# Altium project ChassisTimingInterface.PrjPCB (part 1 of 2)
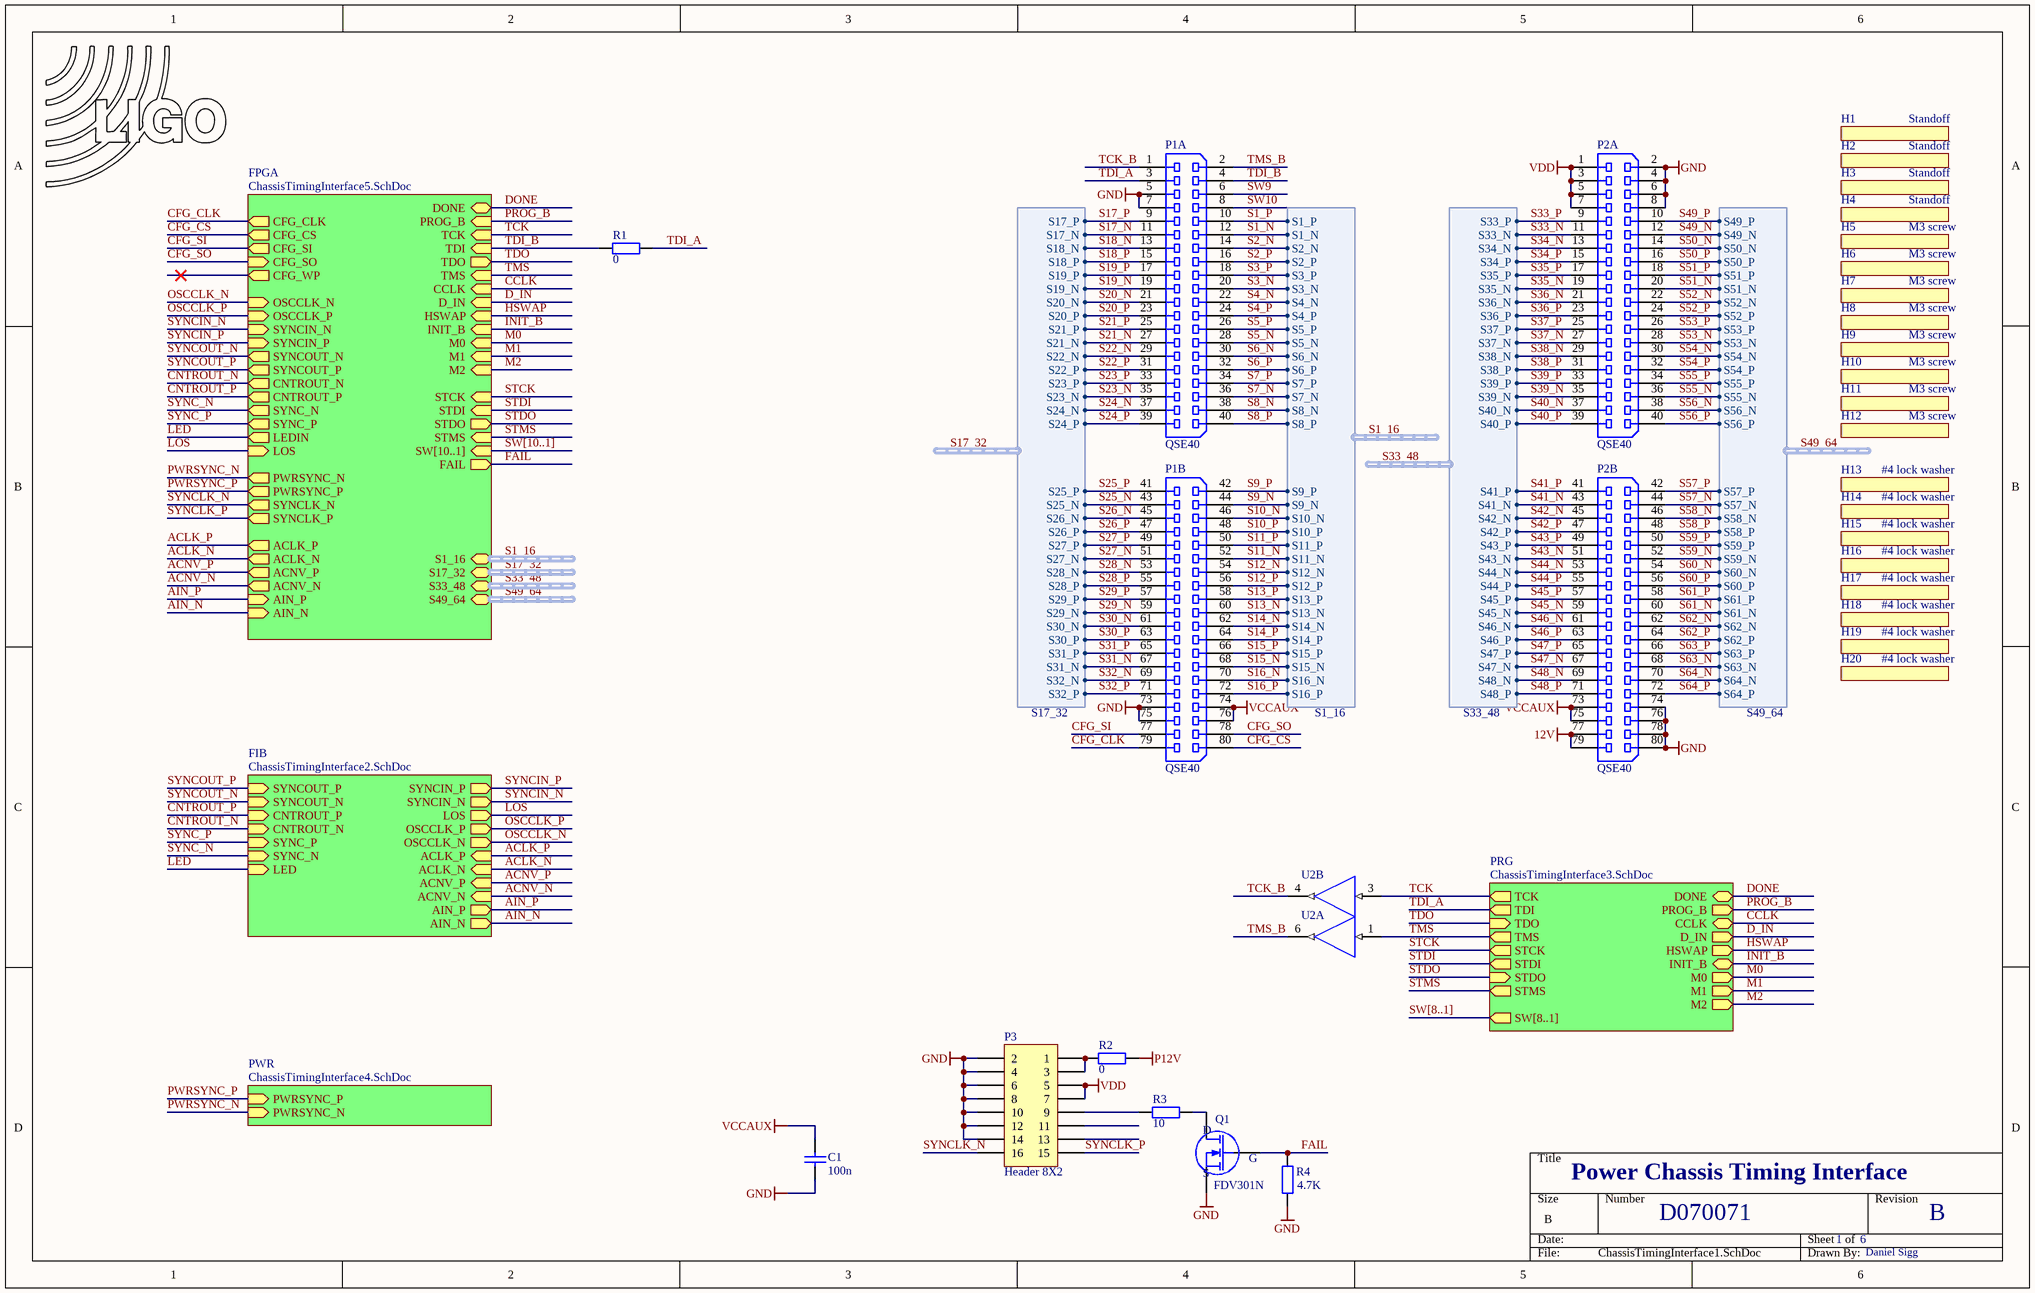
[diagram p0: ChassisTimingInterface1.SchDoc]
6 sheets, 254 parts. Net scope: hierarchical (ports join the sheet entries above them; power ports are global).
Board file: ChassisTimingInterface.PcbDoc
Sheets:
  ChassisTimingInterface1.SchDoc
    FIB = ChassisTimingInterface2.SchDoc
    PWR = ChassisTimingInterface4.SchDoc
    PRG = ChassisTimingInterface3.SchDoc
    FPGA = ChassisTimingInterface5.SchDoc
      U_FPGA_U1_Auto = FPGA_U1_Auto.SchDoc

## Sheet ChassisTimingInterface1.SchDoc: D070071
size B; Engineer: Daniel Sigg; Revision: B; SheetNumber: 1; SheetTotal: 6; PageSetup: Record=PageOptions|CenterHorizontal=True|CenterVertical=True|PrintScale=0.72|XCorrection=1.00|YCorrection=1.00|PrintKind=0|BorderSize=5000000|LeftOffset=0|BottomOffset=0|Orientation=2|PaperLength=1000|PaperWidth=1000|Scale=100|PaperSource=7|PrintQuality=-4|MediaType=1|DitherType=10|PaperKind=Tabloid|PrintScaleMode=1

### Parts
C1  100n  [CC2013-0805]
H1  Standoff  (mechanical)
H2  Standoff  (mechanical)
H3  Standoff  (mechanical)
H4  Standoff  (mechanical)
H5  M3 screw  (mechanical)
H6  M3 screw  (mechanical)
H7  M3 screw  (mechanical)
H8  M3 screw  (mechanical)
H9  M3 screw  (mechanical)
H10  M3 screw  (mechanical)
H11  M3 screw  (mechanical)
H12  M3 screw  (mechanical)
H13  #4 lock washer  (mechanical)
H14  #4 lock washer  (mechanical)
H15  #4 lock washer  (mechanical)
H16  #4 lock washer  (mechanical)
H17  #4 lock washer  (mechanical)
H18  #4 lock washer  (mechanical)
H19  #4 lock washer  (mechanical)
H20  #4 lock washer  (mechanical)
LOGO1  LIGO logo  [LIGO_LOGO]  (value not drawn)  (no BOM)
P1  QSE40  [QSE040]  (parts A,B of 2)
P2  QSE40  [QSE040]  (parts A,B of 2)
P3  Header 8X2  [HDR2X8]
Q1  FDV301N  [SO-G3/C2.25]
R1  0  [CR2012-0805]
R2  0  [CR2012-0805]
R3  10  [CR2012-0805]
R4  4.7K  [CR2012-0805]
U2  SN74LVC2G34  [SO-G6/E2.4]  (value not drawn)  (parts A,B of 2)

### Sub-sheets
FIB = ChassisTimingInterface2.SchDoc: SYNCIN_P (out), SYNCIN_N (out), SYNCOUT_P (in), SYNCOUT_N (in), LOS (out), OSCCLK_P (out), OSCCLK_N (out), CNTROUT_P (in), CNTROUT_N (in), SYNC_P (in), SYNC_N (in), LED (in), AIN_P (out), ACLK_P (in), AIN_N (out), ACNV_N (in), ACLK_N (in), ACNV_P (in)
FPGA = ChassisTimingInterface5.SchDoc: CCLK (in), CFG_CLK (out), CFG_CS (out), CFG_SI (out), CFG_SO (in), CFG_WP (out), CNTROUT_N (out), CNTROUT_P (out), D_IN (in), HSWAP (in), INIT_B (in), LEDIN (out), LOS (in), M0 (in), M1 (in), M2 (in), OSCCLK_N (in), OSCCLK_P (in), PWRSYNC_N (out), PWRSYNC_P (out), STCK (in), STDI (in), STDO (out), STMS (in), SW[10..1] (in), SYNC_N (out), SYNC_P (out), SYNCIN_N (in), SYNCIN_P (in), SYNCLK_N (out), SYNCLK_P (out), SYNCOUT_N (out), SYNCOUT_P (out), DONE (bidir), PROG_B (in), TCK (in), TDI (in), TDO (out), TMS (in), FAIL (out), ACLK_N (out), ACLK_P (out), ACNV_N (out), ACNV_P (out), AIN_N (in), AIN_P (in), S1_16 (harness S1_16), S17_32 (harness S17_32), S33_48 (harness S33_48), S49_64 (harness S49_64)
PRG = ChassisTimingInterface3.SchDoc: STCK (out), STDI (out), STDO (in), STMS (out), TCK (out), TDI (out), TDO (in), TMS (out), CCLK (bidir), D_IN (out), DONE (bidir), HSWAP (out), INIT_B (bidir), M0 (out), PROG_B (out), SW[8..1] (out), M1 (out), M2 (out)
PWR = ChassisTimingInterface4.SchDoc: PWRSYNC_P (in), PWRSYNC_N (in)

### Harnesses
S1_16: S1_N, S1_P, S2_N, S2_P, S3_N, S3_P, S4_N, S4_P, S5_N, S5_P, S6_N, S6_P, S7_N, S7_P, S8_N, S8_P, S9_N, S9_P, S10_N, S10_P, S11_N, S11_P, S12_N, S12_P, S13_N, S13_P, S14_N, S14_P, S15_N, S15_P, S16_N, S16_P
S17_32: S17_N, S17_P, S18_N, S18_P, S19_N, S19_P, S20_N, S20_P, S21_N, S21_P, S22_N, S22_P, S23_N, S23_P, S24_N, S24_P, S25_N, S25_P, S26_N, S26_P, S27_N, S27_P, S28_N, S28_P, S29_N, S29_P, S30_N, S30_P, S31_N, S31_P, S32_N, S32_P
S33_48: S33_P, S33_N, S34_P, S34_N, S35_P, S35_N, S36_N, S36_P, S37_P, S37_N, S38_N, S38_P, S39_P, S39_N, S40_N, S40_P, S41_P, S41_N, S42_N, S42_P, S43_P, S43_N, S44_N, S44_P, S45_P, S45_N, S46_N, S46_P, S47_P, S47_N, S48_N, S48_P
S49_64: S49_P, S49_N, S50_N, S50_P, S51_P, S51_N, S52_N, S52_P, S53_P, S53_N, S54_N, S54_P, S55_P, S55_N, S56_N, S56_P, S57_P, S57_N, S58_N, S58_P, S59_P, S59_N, S60_N, S60_P, S61_P, S61_N, S62_N, S62_P, S63_P, S63_N, S64_N, S64_P

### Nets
12V: P2.77 P2.79
GND: C1.1 P1.5 P1.7 P1.73 P1.75 P1.81 P1.82 P1.83 P1.84 P1.85 P1.86 P1.87 P1.88 P2.2 P2.4 P2.6 P2.8 P2.74 P2.76 P2.78 P2.80 P2.81 P2.82 P2.83 P2.84 P2.85 P2.86 P2.87 P2.88 P3.2 P3.4 P3.6 P3.8 P3.10 P3.12 P3.14 Q1.2(S) R4.1 U2.2(GND)
P12V: R2.2
VCCAUX: C1.2 P1.74 P1.76 P2.73 P2.75 U2.5(VCC)
VDD: P2.1 P2.3 P2.5 P2.7 P3.5 P3.7
ACLK_N: sheet FIB/ACLK_N, sheet FPGA/ACLK_N
ACLK_P: sheet FIB/ACLK_P, sheet FPGA/ACLK_P
ACNV_N: sheet FIB/ACNV_N, sheet FPGA/ACNV_N
ACNV_P: sheet FIB/ACNV_P, sheet FPGA/ACNV_P
AIN_N: sheet FIB/AIN_N, sheet FPGA/AIN_N
AIN_P: sheet FIB/AIN_P, sheet FPGA/AIN_P
CCLK: sheet PRG/CCLK, sheet FPGA/CCLK
CFG_CLK: P1.79 ; sheet FPGA/CFG_CLK
CFG_CS: P1.80 ; sheet FPGA/CFG_CS
CFG_SI: P1.77 ; sheet FPGA/CFG_SI
CFG_SO: P1.78 ; sheet FPGA/CFG_SO
CNTROUT_N: sheet FIB/CNTROUT_N, sheet FPGA/CNTROUT_N
CNTROUT_P: sheet FIB/CNTROUT_P, sheet FPGA/CNTROUT_P
D_IN: sheet PRG/D_IN, sheet FPGA/D_IN
DONE: sheet PRG/DONE, sheet FPGA/DONE
FAIL: Q1.1(G) R4.2 ; sheet FPGA/FAIL
HSWAP: sheet PRG/HSWAP, sheet FPGA/HSWAP
INIT_B: sheet PRG/INIT_B, sheet FPGA/INIT_B
LED: sheet FIB/LED, sheet FPGA/LEDIN
LOS: sheet FIB/LOS, sheet FPGA/LOS
M0: sheet PRG/M0, sheet FPGA/M0
M1: sheet PRG/M1, sheet FPGA/M1
M2: sheet PRG/M2, sheet FPGA/M2
OSCCLK_N: sheet FIB/OSCCLK_N, sheet FPGA/OSCCLK_N
OSCCLK_P: sheet FIB/OSCCLK_P, sheet FPGA/OSCCLK_P
PROG_B: sheet PRG/PROG_B, sheet FPGA/PROG_B
PWRSYNC_N: sheet PWR/PWRSYNC_N, sheet FPGA/PWRSYNC_N
PWRSYNC_P: sheet PWR/PWRSYNC_P, sheet FPGA/PWRSYNC_P
S1_N: P1.12 ; sheet FPGA/S1_16.S1_N  [project net S1_16.S1_N]
S1_P: P1.10 ; sheet FPGA/S1_16.S1_P  [project net S1_16.S1_P]
S2_N: P1.14 ; sheet FPGA/S1_16.S2_N  [project net S1_16.S2_N]
S2_P: P1.16 ; sheet FPGA/S1_16.S2_P  [project net S1_16.S2_P]
S3_N: P1.20 ; sheet FPGA/S1_16.S3_N  [project net S1_16.S3_N]
S3_P: P1.18 ; sheet FPGA/S1_16.S3_P  [project net S1_16.S3_P]
S4_N: P1.22 ; sheet FPGA/S1_16.S4_N  [project net S1_16.S4_N]
S4_P: P1.24 ; sheet FPGA/S1_16.S4_P  [project net S1_16.S4_P]
S5_N: P1.28 ; sheet FPGA/S1_16.S5_N  [project net S1_16.S5_N]
S5_P: P1.26 ; sheet FPGA/S1_16.S5_P  [project net S1_16.S5_P]
S6_N: P1.30 ; sheet FPGA/S1_16.S6_N  [project net S1_16.S6_N]
S6_P: P1.32 ; sheet FPGA/S1_16.S6_P  [project net S1_16.S6_P]
S7_N: P1.36 ; sheet FPGA/S1_16.S7_N  [project net S1_16.S7_N]
S7_P: P1.34 ; sheet FPGA/S1_16.S7_P  [project net S1_16.S7_P]
S8_N: P1.38 ; sheet FPGA/S1_16.S8_N  [project net S1_16.S8_N]
S8_P: P1.40 ; sheet FPGA/S1_16.S8_P  [project net S1_16.S8_P]
S9_N: P1.44 ; sheet FPGA/S1_16.S9_N  [project net S1_16.S9_N]
S9_P: P1.42 ; sheet FPGA/S1_16.S9_P  [project net S1_16.S9_P]
S10_N: P1.46 ; sheet FPGA/S1_16.S10_N
S10_P: P1.48 ; sheet FPGA/S1_16.S10_P
S11_N: P1.52 ; sheet FPGA/S1_16.S11_N
S11_P: P1.50 ; sheet FPGA/S1_16.S11_P
S12_N: P1.54 ; sheet FPGA/S1_16.S12_N
S12_P: P1.56 ; sheet FPGA/S1_16.S12_P
S13_N: P1.60 ; sheet FPGA/S1_16.S13_N
S13_P: P1.58 ; sheet FPGA/S1_16.S13_P
S14_N: P1.62 ; sheet FPGA/S1_16.S14_N
S14_P: P1.64 ; sheet FPGA/S1_16.S14_P
S15_N: P1.68 ; sheet FPGA/S1_16.S15_N
S15_P: P1.66 ; sheet FPGA/S1_16.S15_P
S16_N: P1.70 ; sheet FPGA/S1_16.S16_N
S16_P: P1.72 ; sheet FPGA/S1_16.S16_P
S17_N: P1.11 ; sheet FPGA/S17_32.S17_N  [project net S17_32.S17_N]
S17_P: P1.9 ; sheet FPGA/S17_32.S17_P  [project net S17_32.S17_P]
S18_N: P1.13 ; sheet FPGA/S17_32.S18_N  [project net S17_32.S18_N]
S18_P: P1.15 ; sheet FPGA/S17_32.S18_P  [project net S17_32.S18_P]
S19_N: P1.19 ; sheet FPGA/S17_32.S19_N  [project net S17_32.S19_N]
S19_P: P1.17 ; sheet FPGA/S17_32.S19_P  [project net S17_32.S19_P]
S20_N: P1.21 ; sheet FPGA/S17_32.S20_N  [project net S17_32.S20_N]
S20_P: P1.23 ; sheet FPGA/S17_32.S20_P  [project net S17_32.S20_P]
S21_N: P1.27 ; sheet FPGA/S17_32.S21_N  [project net S17_32.S21_N]
S21_P: P1.25 ; sheet FPGA/S17_32.S21_P  [project net S17_32.S21_P]
S22_N: P1.29 ; sheet FPGA/S17_32.S22_N  [project net S17_32.S22_N]
S22_P: P1.31 ; sheet FPGA/S17_32.S22_P  [project net S17_32.S22_P]
S23_N: P1.35 ; sheet FPGA/S17_32.S23_N  [project net S17_32.S23_N]
S23_P: P1.33 ; sheet FPGA/S17_32.S23_P  [project net S17_32.S23_P]
S24_N: P1.37 ; sheet FPGA/S17_32.S24_N  [project net S17_32.S24_N]
S24_P: P1.39 ; sheet FPGA/S17_32.S24_P  [project net S17_32.S24_P]
S25_N: P1.43 ; sheet FPGA/S17_32.S25_N  [project net S17_32.S25_N]
S25_P: P1.41 ; sheet FPGA/S17_32.S25_P  [project net S17_32.S25_P]
S26_N: P1.45 ; sheet FPGA/S17_32.S26_N  [project net S17_32.S26_N]
S26_P: P1.47 ; sheet FPGA/S17_32.S26_P  [project net S17_32.S26_P]
S27_N: P1.51 ; sheet FPGA/S17_32.S27_N  [project net S17_32.S27_N]
S27_P: P1.49 ; sheet FPGA/S17_32.S27_P  [project net S17_32.S27_P]
S28_N: P1.53 ; sheet FPGA/S17_32.S28_N  [project net S17_32.S28_N]
S28_P: P1.55 ; sheet FPGA/S17_32.S28_P  [project net S17_32.S28_P]
S29_N: P1.59 ; sheet FPGA/S17_32.S29_N  [project net S17_32.S29_N]
S29_P: P1.57 ; sheet FPGA/S17_32.S29_P  [project net S17_32.S29_P]
S30_N: P1.61 ; sheet FPGA/S17_32.S30_N  [project net S17_32.S30_N]
S30_P: P1.63 ; sheet FPGA/S17_32.S30_P  [project net S17_32.S30_P]
S31_N: P1.67 ; sheet FPGA/S17_32.S31_N  [project net S17_32.S31_N]
S31_P: P1.65 ; sheet FPGA/S17_32.S31_P  [project net S17_32.S31_P]
S32_N: P1.69 ; sheet FPGA/S17_32.S32_N  [project net S17_32.S32_N]
S32_P: P1.71 ; sheet FPGA/S17_32.S32_P  [project net S17_32.S32_P]
S33_N: P2.11 ; sheet FPGA/S33_48.S33_N  [project net S33_48.S33_N]
S33_P: P2.9 ; sheet FPGA/S33_48.S33_P  [project net S33_48.S33_P]
S34_N: P2.13 ; sheet FPGA/S33_48.S34_N  [project net S33_48.S34_N]
S34_P: P2.15 ; sheet FPGA/S33_48.S34_P  [project net S33_48.S34_P]
S35_N: P2.19 ; sheet FPGA/S33_48.S35_N  [project net S33_48.S35_N]
S35_P: P2.17 ; sheet FPGA/S33_48.S35_P  [project net S33_48.S35_P]
S36_N: P2.21 ; sheet FPGA/S33_48.S36_N  [project net S33_48.S36_N]
S36_P: P2.23 ; sheet FPGA/S33_48.S36_P  [project net S33_48.S36_P]
S37_N: P2.27 ; sheet FPGA/S33_48.S37_N  [project net S33_48.S37_N]
S37_P: P2.25 ; sheet FPGA/S33_48.S37_P  [project net S33_48.S37_P]
S38_N: P2.29 ; sheet FPGA/S33_48.S38_N  [project net S33_48.S38_N]
S38_P: P2.31 ; sheet FPGA/S33_48.S38_P  [project net S33_48.S38_P]
S39_N: P2.35 ; sheet FPGA/S33_48.S39_N  [project net S33_48.S39_N]
S39_P: P2.33 ; sheet FPGA/S33_48.S39_P  [project net S33_48.S39_P]
S40_N: P2.37 ; sheet FPGA/S33_48.S40_N  [project net S33_48.S40_N]
S40_P: P2.39 ; sheet FPGA/S33_48.S40_P  [project net S33_48.S40_P]
S41_N: P2.43 ; sheet FPGA/S33_48.S41_N  [project net S33_48.S41_N]
S41_P: P2.41 ; sheet FPGA/S33_48.S41_P  [project net S33_48.S41_P]
S42_N: P2.45 ; sheet FPGA/S33_48.S42_N  [project net S33_48.S42_N]
S42_P: P2.47 ; sheet FPGA/S33_48.S42_P  [project net S33_48.S42_P]
S43_N: P2.51 ; sheet FPGA/S33_48.S43_N  [project net S33_48.S43_N]
S43_P: P2.49 ; sheet FPGA/S33_48.S43_P  [project net S33_48.S43_P]
S44_N: P2.53 ; sheet FPGA/S33_48.S44_N  [project net S33_48.S44_N]
S44_P: P2.55 ; sheet FPGA/S33_48.S44_P  [project net S33_48.S44_P]
S45_N: P2.59 ; sheet FPGA/S33_48.S45_N  [project net S33_48.S45_N]
S45_P: P2.57 ; sheet FPGA/S33_48.S45_P  [project net S33_48.S45_P]
S46_N: P2.61 ; sheet FPGA/S33_48.S46_N  [project net S33_48.S46_N]
S46_P: P2.63 ; sheet FPGA/S33_48.S46_P  [project net S33_48.S46_P]
S47_N: P2.67 ; sheet FPGA/S33_48.S47_N  [project net S33_48.S47_N]
S47_P: P2.65 ; sheet FPGA/S33_48.S47_P  [project net S33_48.S47_P]
S48_N: P2.69 ; sheet FPGA/S33_48.S48_N  [project net S33_48.S48_N]
S48_P: P2.71 ; sheet FPGA/S33_48.S48_P  [project net S33_48.S48_P]
S49_N: P2.12 ; sheet FPGA/S49_64.S49_N  [project net S49_64.S49_N]
S49_P: P2.10 ; sheet FPGA/S49_64.S49_P  [project net S49_64.S49_P]
S50_N: P2.14 ; sheet FPGA/S49_64.S50_N  [project net S49_64.S50_N]
S50_P: P2.16 ; sheet FPGA/S49_64.S50_P  [project net S49_64.S50_P]
S51_N: P2.20 ; sheet FPGA/S49_64.S51_N  [project net S49_64.S51_N]
S51_P: P2.18 ; sheet FPGA/S49_64.S51_P  [project net S49_64.S51_P]
S52_N: P2.22 ; sheet FPGA/S49_64.S52_N  [project net S49_64.S52_N]
S52_P: P2.24 ; sheet FPGA/S49_64.S52_P  [project net S49_64.S52_P]
S53_N: P2.28 ; sheet FPGA/S49_64.S53_N  [project net S49_64.S53_N]
S53_P: P2.26 ; sheet FPGA/S49_64.S53_P  [project net S49_64.S53_P]
S54_N: P2.30 ; sheet FPGA/S49_64.S54_N  [project net S49_64.S54_N]
S54_P: P2.32 ; sheet FPGA/S49_64.S54_P  [project net S49_64.S54_P]
S55_N: P2.36 ; sheet FPGA/S49_64.S55_N  [project net S49_64.S55_N]
S55_P: P2.34 ; sheet FPGA/S49_64.S55_P  [project net S49_64.S55_P]
S56_N: P2.38 ; sheet FPGA/S49_64.S56_N  [project net S49_64.S56_N]
S56_P: P2.40 ; sheet FPGA/S49_64.S56_P  [project net S49_64.S56_P]
S57_N: P2.44 ; sheet FPGA/S49_64.S57_N  [project net S49_64.S57_N]
S57_P: P2.42 ; sheet FPGA/S49_64.S57_P  [project net S49_64.S57_P]
S58_N: P2.46 ; sheet FPGA/S49_64.S58_N  [project net S49_64.S58_N]
S58_P: P2.48 ; sheet FPGA/S49_64.S58_P  [project net S49_64.S58_P]
S59_N: P2.52 ; sheet FPGA/S49_64.S59_N  [project net S49_64.S59_N]
S59_P: P2.50 ; sheet FPGA/S49_64.S59_P  [project net S49_64.S59_P]
S60_N: P2.54 ; sheet FPGA/S49_64.S60_N  [project net S49_64.S60_N]
S60_P: P2.56 ; sheet FPGA/S49_64.S60_P  [project net S49_64.S60_P]
S61_N: P2.60 ; sheet FPGA/S49_64.S61_N  [project net S49_64.S61_N]
S61_P: P2.58 ; sheet FPGA/S49_64.S61_P  [project net S49_64.S61_P]
S62_N: P2.62 ; sheet FPGA/S49_64.S62_N  [project net S49_64.S62_N]
S62_P: P2.64 ; sheet FPGA/S49_64.S62_P  [project net S49_64.S62_P]
S63_N: P2.68 ; sheet FPGA/S49_64.S63_N  [project net S49_64.S63_N]
S63_P: P2.66 ; sheet FPGA/S49_64.S63_P  [project net S49_64.S63_P]
S64_N: P2.70 ; sheet FPGA/S49_64.S64_N  [project net S49_64.S64_N]
S64_P: P2.72 ; sheet FPGA/S49_64.S64_P  [project net S49_64.S64_P]
STCK: sheet PRG/STCK, sheet FPGA/STCK
STDI: sheet PRG/STDI, sheet FPGA/STDI
STDO: sheet PRG/STDO, sheet FPGA/STDO
STMS: sheet PRG/STMS, sheet FPGA/STMS
SW9: P1.6
SW10: P1.8
SYNC_N: sheet FIB/SYNC_N, sheet FPGA/SYNC_N
SYNC_P: sheet FIB/SYNC_P, sheet FPGA/SYNC_P
SYNCIN_N: sheet FIB/SYNCIN_N, sheet FPGA/SYNCIN_N
SYNCIN_P: sheet FIB/SYNCIN_P, sheet FPGA/SYNCIN_P
SYNCLK_N: P3.16 ; sheet FPGA/SYNCLK_N
SYNCLK_P: P3.15 ; sheet FPGA/SYNCLK_P
SYNCOUT_N: sheet FIB/SYNCOUT_N, sheet FPGA/SYNCOUT_N
SYNCOUT_P: sheet FIB/SYNCOUT_P, sheet FPGA/SYNCOUT_P
TCK: U2.3(2A) ; sheet PRG/TCK, sheet FPGA/TCK
TCK_B: P1.1 U2.4(2Y)
TDI_A: P1.3 R1.2 ; sheet PRG/TDI
TDI_B: P1.4 R1.1 ; sheet FPGA/TDI
TDO: sheet PRG/TDO, sheet FPGA/TDO
TMS: U2.1(1A) ; sheet PRG/TMS, sheet FPGA/TMS
TMS_B: P1.2 U2.6(1Y)
NetP3_1: P3.1 P3.3 R2.1
NetP3_9: P3.9 R3.1
NetQ1_3: Q1.3(D) R3.2

Not connected (* = marked no-connect by the designer): P3 11 13

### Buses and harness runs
bus SW[8..1] = sheet PRG/SW[8..1]
bus SW[10..1] = sheet FPGA/SW[10..1]
harness S1_16 = sheet FPGA/S1_16
harness S17_32 = sheet FPGA/S17_32
harness S33_48 = sheet FPGA/S33_48
harness S49_64 = sheet FPGA/S49_64

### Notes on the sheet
- Power Chassis Timing Interface
- D070071
- B
- Daniel Sigg

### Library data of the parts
C1 = ChipCap: Capacitor, surface mount; Part Number: 478-1395-1-ND; Tolerance: 10%
H1-H4 = Partlist: Mounting hardware; Part Number: 728-FM1258-3005-A
H5-H12 = Partlist: Mounting hardware; Part Number: 48SM003
H13-H20 = Partlist: Mounting hardware; Part Number: 5721-LWI6SS
LOGO1 = LIGO_logo
P1 P2 = SAMTEC_QSE40: Samtec hi-speed socket, 0.8mm, 80 pins; Part Number: SAM8124-ND
P3 = Header 8X2: Header, 8-Pin, Dual row; Part Number: A33164-ND
Q1 = FDV301N: FDV301N, Digital FET, N-channel, SOT23; Part Number: FDV301NCT-ND
R1 R2 = ChipRes1: Resistor, surface mount; Part Number: 311-0.0ARCT-ND; Tolerance: 0.5%
R3 = ChipRes1: Resistor, surface mount; Part Number: RR12Q10DCT-ND; Tolerance: 0.5%
R4 = ChipRes1: Resistor, surface mount; Part Number: RR12P4.7KDCT-ND; Tolerance: 0.5%
U2 = SN74LVC2G34: Dual buffer; Part Number: 296-13496-1-ND

## Sheet ChassisTimingInterface2.SchDoc: D070071
size B; Revision: B; SheetNumber: 2; SheetTotal: 6
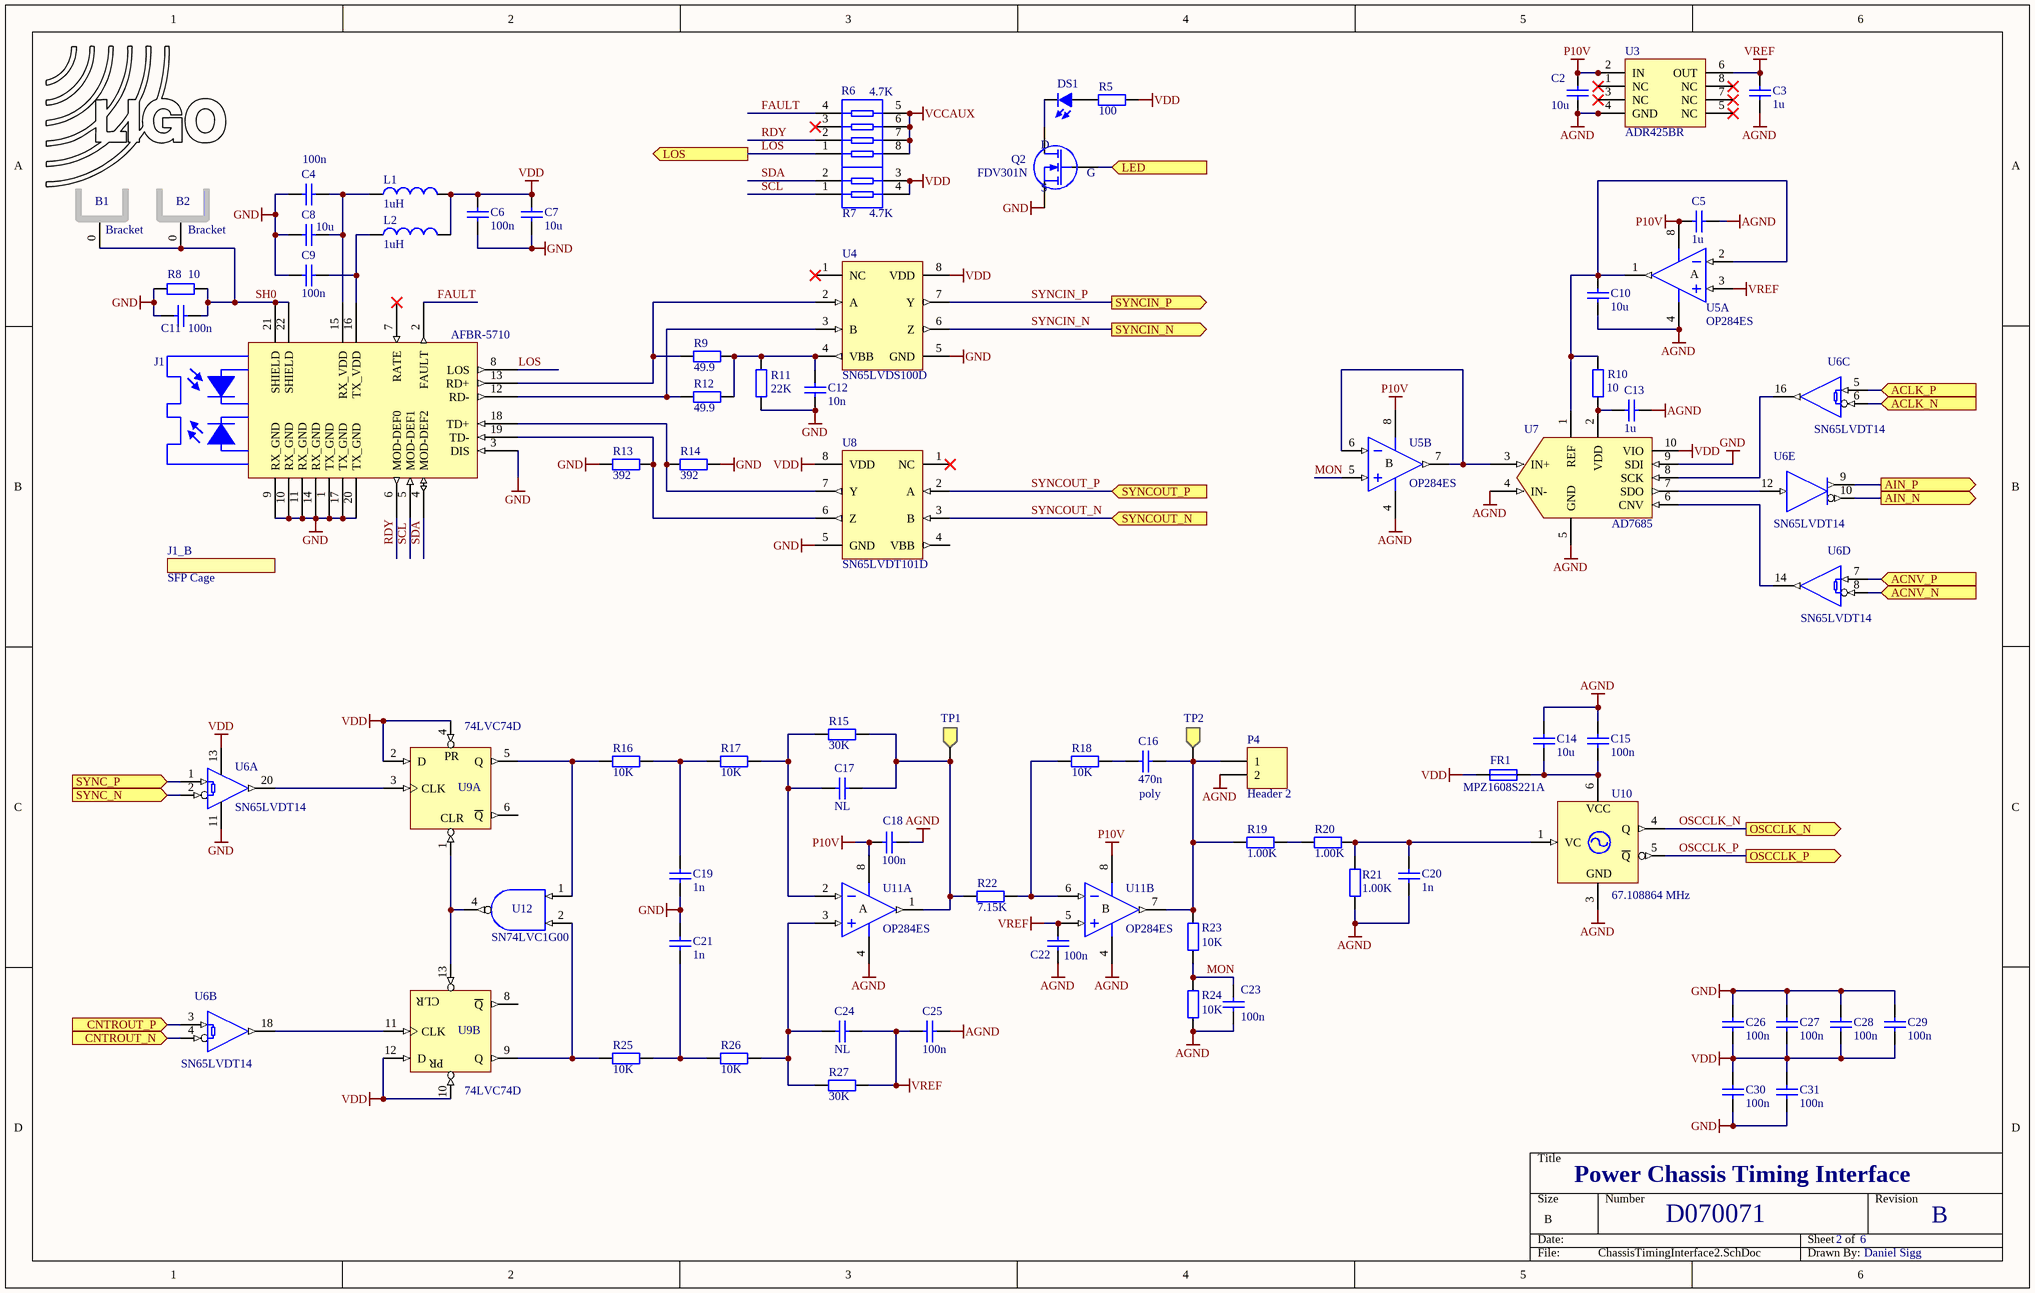
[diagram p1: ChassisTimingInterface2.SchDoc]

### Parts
B1  Bracket  [Bracket-RA_7774]
B2  Bracket  [Bracket-RA_7774]
C2  10u  [CC3216-1206]
C3  1u  [CC2013-0805]
C4  100n  [CC2013-0805]
C5  1u  [CC2013-0805]
C6  100n  [CC2013-0805]
C7  10u  [CC2013-0805]
C8  10u  [CC2013-0805]
C9  100n  [CC2013-0805]
C10  10u  [CC3216-1206]
C11  100n  [CC2013-0805]
C12  10n  [CC2013-0805]
C13  1u  [CC2013-0805]
C14  10u  [CC2013-0805]
C15  100n  [CC2013-0805]
C16  470n  [CA053035]
C17  NL  [CC2013-0805]
C18  100n  [CC2013-0805]
C19  1n  [CC2013-0805]
C20  1n  [CC2013-0805]
C21  1n  [CC2013-0805]
C22  100n  [CC2013-0805]
C23  100n  [CC2013-0805]
C24  NL  [CC2013-0805]
C25  100n  [CC2013-0805]
C26  100n  [CC2013-0805]
C27  100n  [CC2013-0805]
C28  100n  [CC2013-0805]
C29  100n  [CC2013-0805]
C30  100n  [CC2013-0805]
C31  100n  [CC2013-0805]
DS1  LED  [LED-2]  (value not drawn)
FR1  MPZ1608S221A  [CL1608-0603]
J1  AFBR-5710  [MSA/SFP2x10]
J1_B  SFP Cage  (mechanical)
L1  1uH  [CL2520-1008]
L2  1uH  [CL2520-1008]
LOGO2  LIGO logo  [LIGO_LOGO]  (value not drawn)  (graphical)
P4  Header 2  [HDR1X2]
Q2  FDV301N  [SO-G3/C2.25]
R5  100  [CR2012-0805]
R6  value 4.7K  [RES8-0.8]  (hidden comment: Resistor Array)
R7  value 4.7K  [RES4-0.8]  (hidden comment: Resistor Array)
R8  10  [CR2012-0805]
R9  49.9  [CR2012-0805]
R10  10  [CR2012-0805]
R11  22K  [CR2012-0805]
R12  49.9  [CR2012-0805]
R13  392  [CR2012-0805]
R14  392  [CR2012-0805]
R15  30K  [CR2012-0805]
R16  10K  [CR2012-0805]
R17  10K  [CR2012-0805]
R18  10K  [CR2012-0805]
R19  1.00K  [CR2012-0805]
R20  1.00K  [CR2012-0805]
R21  1.00K  [CR2012-0805]
R22  7.15K  [CR2012-0805]
R23  10K  [CR2012-0805]
R24  10K  [CR2012-0805]
R25  10K  [CR2012-0805]
R26  10K  [CR2012-0805]
R27  30K  [CR2012-0805]
TP1  Testpoint  [TP1]  (value not drawn)
TP2  Testpoint  [TP1]  (value not drawn)
U3  ADR425BR  [SO-G8]
U4  SN65LVDS100D  [SO-G8]
U5  OP284ES  [SO-G8]  (parts A,B of 2)
U6  SN65LVDT14  [TSSO6x6-G20/D6.6]  (parts A,B,C,D,E of 5)
U7  AD7685  [TSSO3x5-G10]
U8  SN65LVDT101D  [SO-G8]
U9  74LVC74D  [SO-G14]  (parts A,B of 2)
U10  67.108864 MHz  [VECTRON_C5310]
U11  OP284ES  [SO-G8]  (parts A,B of 2)
U12  SN74LVC1G00  [SO-G5/E2.4]

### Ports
ACLK_N (in), ACLK_P (in), ACNV_N (in), ACNV_P (in), AIN_N (out), AIN_P (out), CNTROUT_N (in), CNTROUT_P (in), LED (in), LOS (out), OSCCLK_N (out), OSCCLK_P (out), SYNC_N (in), SYNC_P (in), SYNCIN_N (out), SYNCIN_P (out), SYNCOUT_N (in), SYNCOUT_P (in)

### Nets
AGND: C2.2 C3.1 C5.1 C10.1 C13.2 C14.1 C15.1 C18.1 C20.2 C22.1 C23.1 C25.1 P4.2 R21.2 R24.2 U3.4(GND) U5.4(V-) U7.4(IN-) U7.5(GND) U10.3(GND) U11.4(V-)
GND: C4.1 C6.1 C7.1 C8.1 C9.1 C11.2 C12.1 C19.2 C21.1 C26.2 C27.2 C28.2 C29.2 C30.1 C31.1 J1.1(TX_GND) J1.3(DIS) J1.9(RX_GND) J1.10(RX_GND) J1.11(RX_GND) J1.14(RX_GND) J1.17(TX_GND) J1.20(TX_GND) Q2.2(S) R8.2 R11.2 R13.1 R14.2 U4.5(GND) U6.11(GND) U6.15(GND) U6.19(GND) U7.9(SDI) U8.5(GND) U9.7(GND) U12.3(GND)
P10V: C2.1 C5.2 C18.2 U3.2(IN) U5.8(V+) U11.8(V+)
VCCAUX: R6.5 R6.6 R6.7 R6.8
VDD: C6.2 C7.2 C26.1 C27.1 C28.1 C29.1 C30.2 C31.2 FR1.1 L1.2 L2.2 R5.2 R7.3 R7.4 U4.8(VDD) U6.13(VCC) U6.17(VCC) U7.10(VIO) U8.8(VDD) U9.2(D) U9.4(PR) U9.10(PR) U9.12(D) U9.14(VDD) U12.5(VDD)
VREF: C3.2 C22.2 C24.1 C25.2 R27.2 U3.6(OUT) U5.3(IN+) U11.5(IN+)
ACLK_N: U6.6(3B) ; port ACLK_N
ACLK_P: U6.5(3A) ; port ACLK_P
ACNV_N: U6.8(4B) ; port ACNV_N
ACNV_P: U6.7(4A) ; port ACNV_P
AIN_N: U6.10(5Z) ; port AIN_N
AIN_P: U6.9(5Y) ; port AIN_P
CNTROUT_N: U6.4(2B) ; port CNTROUT_N
CNTROUT_P: U6.3(2A) ; port CNTROUT_P
FAULT: J1.2(FAULT) R6.4
LED: Q2.1(G) ; port LED
LOS: J1.8(LOS) R6.1 ; port LOS
MON: C23.2 R23.2 R24.1 U5.5(IN+)
OSCCLK_N: U10.4(Q) ; port OSCCLK_N
OSCCLK_P: U10.5(~{Q}) ; port OSCCLK_P
RDY: J1.6(MOD-DEF0) R6.2
SCL: J1.5(MOD-DEF1) R7.1
SDA: J1.4(MOD-DEF2) R7.2
SH0: B1.0(GND) B2.0(GND) C11.1 J1.21(SHIELD) J1.22(SHIELD) R8.1
SYNC_N: U6.2(1B) ; port SYNC_N
SYNC_P: U6.1(1A) ; port SYNC_P
SYNCIN_N: U4.6(Z) ; port SYNCIN_N
SYNCIN_P: U4.7(Y) ; port SYNCIN_P
SYNCOUT_N: U8.3(B) ; port SYNCOUT_N
SYNCOUT_P: U8.2(A) ; port SYNCOUT_P
NetC4_2: C4.2 C8.2 J1.15(RX_VDD) L1.1
NetC9_2: C9.2 J1.16(TX_VDD) L2.1
NetC10_2: C10.2 R10.2 U5.1(OUT) U5.2(IN-) U7.1(REF)
NetC12_2: C12.2 R9.1 R11.1 R12.1 U4.4(VBB)
NetC13_1: C13.1 R10.1 U7.2(VDD)
NetC14_2: C14.2 C15.2 FR1.2 U10.6(VDD)
NetC16_1: C16.1 R18.2
NetC16_2: C16.2 P4.1 R19.2 R23.1 TP2.1 U11.7(OUT)
NetC17_1: C17.1 R15.2 R22.1 TP1.1 U11.1(OUT)
NetC17_2: C17.2 R15.1 R17.2 U11.2(IN-)
NetC19_1: C19.1 R16.2 R17.1
NetC20_1: C20.1 R20.1 R21.1 U10.1(VC)
NetC21_2: C21.2 R25.2 R26.1
NetC24_2: C24.2 R26.2 R27.1 U11.3(IN+)
NetDS1_1: DS1.1(K) Q2.3(D)
NetDS1_2: DS1.2(A) R5.1
NetJ1_12: J1.12(RD-) R12.2 U4.3(B)
NetJ1_13: J1.13(RD+) R9.2 U4.2(A)
NetJ1_18: J1.18(TD+) R14.1 U8.7(Y)
NetJ1_19: J1.19(TD-) R13.2 U8.6(Z)
NetR16_1: R16.1 U9.5(Q) U12.1
NetR18_1: R18.1 R22.2 U11.6(IN-)
NetR19_1: R19.1 R20.2
NetR25_1: R25.1 U9.9(Q) U12.2
NetU5_6: U5.6(IN-) U5.7(OUT) U7.3(IN+)
NetU6_12: U6.12(5D) U7.7(SDO)
NetU6_14: U6.14(4R) U7.6(CNV)
NetU6_16: U6.16(3R) U7.8(SCK)
NetU6_18: U6.18(2R) U9.11(CLK)
NetU6_20: U6.20(1R) U9.3(CLK)
NetU9_1: U9.1(CLR) U9.13(CLR) U12.4

Not connected (* = marked no-connect by the designer): J1 7(RATE)* 23(POST) 24(POST); R6 3*; U3 1(NC)* 3(NC)* 5(NC)* 7(NC)* 8(NC)*; U4 1(NC)*; U8 1(NC)* 4(VBB); U9 6(~{Q}) 8(~{Q}); U10 2(NC)

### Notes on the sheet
- (near C16) poly
- Power Chassis Timing Interface
- D070071
- B
- Daniel Sigg

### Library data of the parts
B1 B2 = Bracket_7774: Keystone Electronics right-angle 4-40 steel, 7774; Part Number: 534-7774
C2 = ChipCap: Capacitor, surface mount; Part Number: PCC2414CT-ND; Tolerance: 10%
C3 = ChipCap: Capacitor, surface mount; Part Number: PCC2319CT-ND; Tolerance: 10%
C4 C6 C9 = ChipCap: Capacitor, surface mount; Part Number: 478-1395-1-ND; Tolerance: 10%; Voltage Rating: 10V
C5 = ChipCap: Capacitor, surface mount; Part Number: PCC2319CT-ND; Tolerance: 10%; Voltage Rating: 25V
C7 C8 C14 = ChipCap: Capacitor, surface mount; Part Number: 490-1709-1-ND; Tolerance: 10%; Voltage Rating: 10V
C10 = ChipCap: Capacitor, surface mount; Part Number: PCC2414CT-ND; Tolerance: 10%; Voltage Rating: 50V
C11 C18 C22 C23 C25-C31 = ChipCap: as C1 on sheet ChassisTimingInterface1
C12 = ChipCap: Capacitor, surface mount; Part Number: 490-1642-1-ND; Tolerance: 10%; Voltage Rating: 10V
C13 = ChipCap: Capacitor, surface mount; Part Number: PCC2319CT-ND; Tolerance: 10%; Voltage Rating: 50V
C15 = ChipCap: Capacitor, surface mount; Part Number: 478-1395-1-ND; Tolerance: 10%; Voltage Rating: 50V
C16 = CapFilmAxial: Film Capacitor, axial lead; Part Number: MCO2B474G; Tolerance: 2%; Voltage Rating: 50V
C17 C24 = ChipCap: Capacitor, surface mount; Tolerance: 10%
C19-C21 = ChipCap: Capacitor, surface mount; Part Number: 311-1122-1-ND; Tolerance: 10%
DS1 = LED: Panel mount LED; Part Number: 67-1270-ND
FR1 = BLM31PG121SN1: ferrite bead, 22Ohm at 100MHz, 603; Part Number: 445-1565-1-ND
J1 = AFBR-5710: fiber optic transceiver, 1.25GB/s, MM, LC, SFP; Part Number: WM1633CT-ND
J1_B = Partlist: Part Number: WM1634-ND
L1 L2 = ChipInductor: Inductor; Part Number: 1008LS-102XJLB
LOGO2 = LIGO_logo
P4 = Header 2: Header, 2-Pin; Part Number: A26565-ND
Q2 = FDV301N: as Q1 on sheet ChassisTimingInterface1
R5 = ChipRes1: Resistor, surface mount; Part Number: RR12P100DCT-ND; Tolerance: 0.5%
R6 = RES4_ARRAY: Resistor Network, parallel, 4 resistors; Part Number: 742C083472JPCT-ND
R7 = RES2_ARRAY: Resistor Network, parallel, 2 resistors; Part Number: 742C043472JCT-ND
R8 R10 = ChipRes1: as R3 on sheet ChassisTimingInterface1
R9 R12 = ChipRes1: Resistor, surface mount; Part Number: RR12Q49.9DCT-ND; Tolerance: 0.5%
R11 = ChipRes1: Resistor, surface mount; Part Number: RR12P22.0KDCT-ND; Tolerance: 0.5%
R13 R14 = ChipRes1: Resistor, surface mount; Part Number: RR12P392DCT-ND; Tolerance: 0.5%
R15 R27 = ChipRes1: Resistor, surface mount; Part Number: RG20P30.0KBCT-ND; Tolerance: 0.1%
R16-R18 R23-R26 = ChipRes1: Resistor, surface mount; Part Number: RG20P10.0KBCT-ND; Tolerance: 0.1%
R19-R21 = ChipRes1: Resistor, surface mount; Part Number: RG20P1.0KBCT-ND; Tolerance: 0.1%
R22 = ChipRes1: Resistor, surface mount; Part Number: RG20P7.15KBCT-ND; Tolerance: 0.1%
TP1 TP2 = TP_SIGNAL: Testpoint, yellow; Part Number: 5009K-ND
U3 = ADR292ER: Low-Noise Micropower Precision Voltage Reference; Part Number: ADR425BRZ-ND
U4 = SN65LVDS100: DIFF TRANSLATOR; Part Number: 296-13624-5-ND
U5 U11 = OP284ES: Precision Rail-to-Rail Input and Output Operational Amplifier; Part Number: OP284ESZ-ND
U6 = SN65LVDT14: Part Number: 296-19499-1-ND
U7 = AD7685: 16 bit ADC, 250kSPS, pseudo differential, serial; Part Number: AD7685BRMZ-ND
U8 = SN65LVDS100: DIFF TRANSLATOR; Part Number: 296-15391-5-ND
U9 = 74F74PC: Dual D-Type Positive Edge-Triggered Flip-Flop; Part Number: 296-1240-5-ND
U10 = VECTRON_C5310: Voltage controlled crystal oscillator; Part Number: C5310-D105-SV033-RFL-B1-67.108864MHz
U12 = SN74LVC1G00: Part Number: 296-9845-1-ND

## Sheet ChassisTimingInterface4.SchDoc: D070071
size B; Revision: B; SheetNumber: 4; SheetTotal: 6
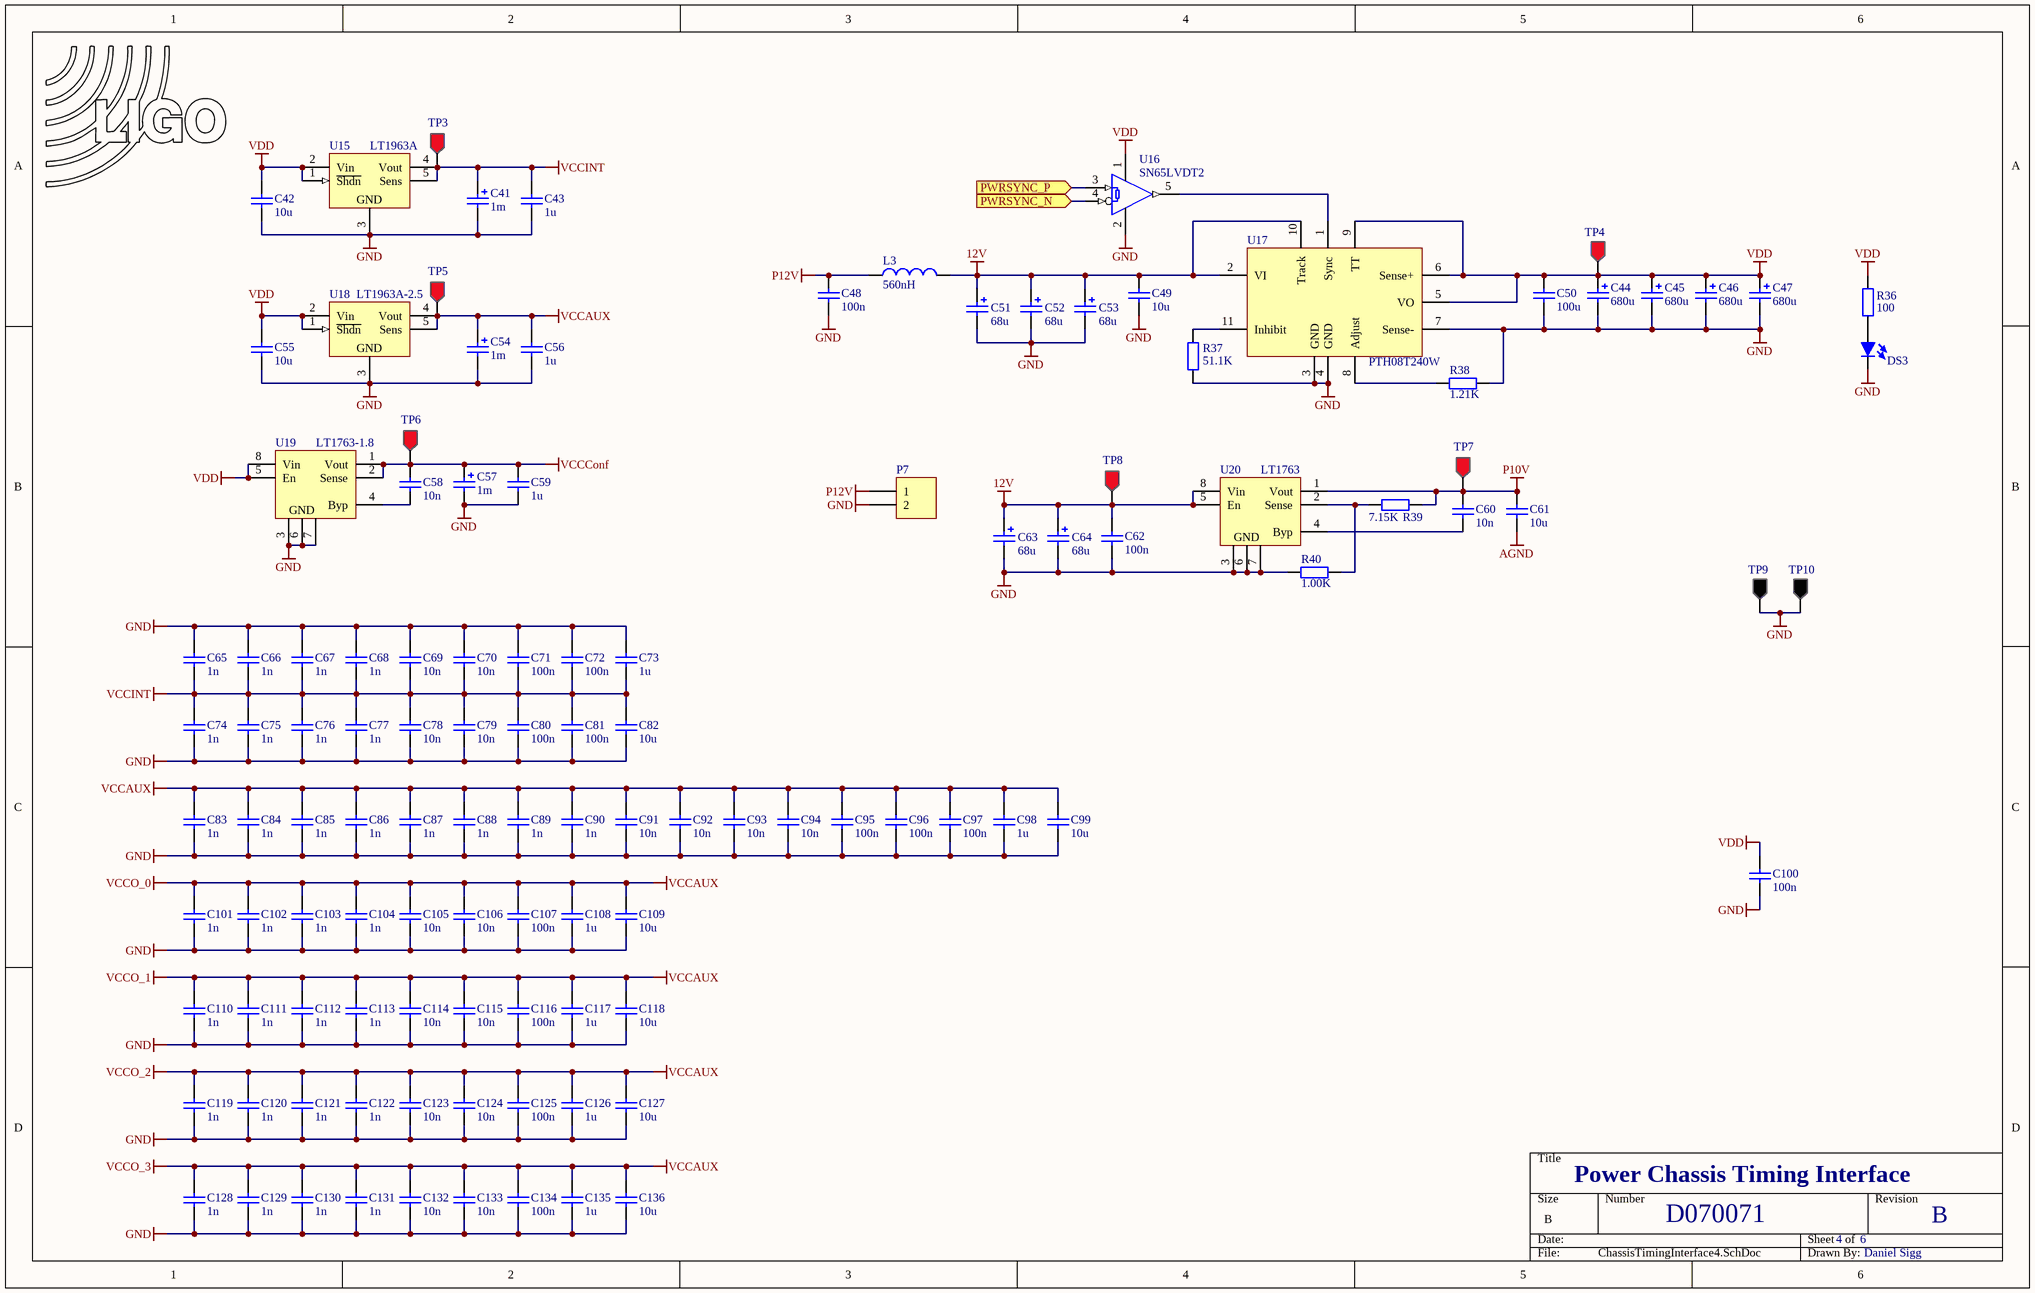
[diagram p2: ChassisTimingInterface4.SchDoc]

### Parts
C41  1m  [TC7343-2917]
C42  10u  [CC3216-1206]
C43  1u  [CC2013-0805]
C44  680u  [TC7343-2917]
C45  680u  [TC7343-2917]
C46  680u  [TC7343-2917]
C47  680u  [TC7343-2917]
C48  100n  [CC2013-0805]
C49  10u  [CC3216-1206]
C50  100u  [CC3216-1206]
C51  68u  [TC7343-2917]
C52  68u  [TC7343-2917]
C53  68u  [TC7343-2917]
C54  1m  [TC7343-2917]
C55  10u  [CC3216-1206]
C56  1u  [CC2013-0805]
C57  1m  [TC7343-2917]
C58  10n  [CC2013-0805]
C59  1u  [CC2013-0805]
C60  10n  [CC2013-0805]
C61  10u  [CC3216-1206]
C62  100n  [CC2013-0805]
C63  68u  [TC7343-2917]
C64  68u  [TC7343-2917]
C65  1n  [CC1005-0402]
C66  1n  [CC1005-0402]
C67  1n  [CC1005-0402]
C68  1n  [CC1005-0402]
C69  10n  [CC1005-0402]
C70  10n  [CC1005-0402]
C71  100n  [CC1005-0402]
C72  100n  [CC1005-0402]
C73  1u  [CC1608-0603]
C74  1n  [CC1005-0402]
C75  1n  [CC1005-0402]
C76  1n  [CC1005-0402]
C77  1n  [CC1005-0402]
C78  10n  [CC1005-0402]
C79  10n  [CC1005-0402]
C80  100n  [CC1005-0402]
C81  100n  [CC1005-0402]
C82  10u  [CC2013-0805]
C83  1n  [CC1005-0402]
C84  1n  [CC1005-0402]
C85  1n  [CC1005-0402]
C86  1n  [CC1005-0402]
C87  1n  [CC1005-0402]
C88  1n  [CC1005-0402]
C89  1n  [CC1005-0402]
C90  1n  [CC1005-0402]
C91  10n  [CC1005-0402]
C92  10n  [CC1005-0402]
C93  10n  [CC1005-0402]
C94  10n  [CC1005-0402]
C95  100n  [CC1005-0402]
C96  100n  [CC1005-0402]
C97  100n  [CC1005-0402]
C98  1u  [CC1608-0603]
C99  10u  [CC2013-0805]
C100  100n  [CC2013-0805]
C101  1n  [CC1005-0402]
C102  1n  [CC1005-0402]
C103  1n  [CC1005-0402]
C104  1n  [CC1005-0402]
C105  10n  [CC1005-0402]
C106  10n  [CC1005-0402]
C107  100n  [CC1005-0402]
C108  1u  [CC1608-0603]
C109  10u  [CC2013-0805]
C110  1n  [CC1005-0402]
C111  1n  [CC1005-0402]
C112  1n  [CC1005-0402]
C113  1n  [CC1005-0402]
C114  10n  [CC1005-0402]
C115  10n  [CC1005-0402]
C116  100n  [CC1005-0402]
C117  1u  [CC1608-0603]
C118  10u  [CC2013-0805]
C119  1n  [CC1005-0402]
C120  1n  [CC1005-0402]
C121  1n  [CC1005-0402]
C122  1n  [CC1005-0402]
C123  10n  [CC1005-0402]
C124  10n  [CC1005-0402]
C125  100n  [CC1005-0402]
C126  1u  [CC1608-0603]
C127  10u  [CC2013-0805]
C128  1n  [CC1005-0402]
C129  1n  [CC1005-0402]
C130  1n  [CC1005-0402]
C131  1n  [CC1005-0402]
C132  10n  [CC1005-0402]
C133  10n  [CC1005-0402]
C134  100n  [CC1005-0402]
C135  1u  [CC1608-0603]
C136  10u  [CC2013-0805]
DS3  LED  [LED-2]  (value not drawn)
L3  560nH  [MVR1251]
LOGO4  LIGO logo  [LIGO_LOGO]  (value not drawn)  (graphical)
P7  TBlock_5.08_2  [TBLOCK-5.08-2]  (value not drawn)
R36  100  [CR2012-0805]
R37  51.1K  [CR2012-0805]
R38  1.21K  [CR2012-0805]
R39  7.15K  [CR2012-0805]
R40  1.00K  [CR2012-0805]
TP3  Testpoint  [TP1]  (value not drawn)
TP4  Testpoint  [TP1]  (value not drawn)
TP5  Testpoint  [TP1]  (value not drawn)
TP6  Testpoint  [TP1]  (value not drawn)
TP7  Testpoint  [TP1]  (value not drawn)
TP8  Testpoint  [TP1]  (value not drawn)
TP9  Testpoint  [TP1]  (value not drawn)
TP10  Testpoint  [TP1]  (value not drawn)
U15  LT1963A  [TO-263]
U16  SN65LVDT2  [SO-G5/E2.4]
U17  PTH08T240W  [PTH08T240W]
U18  LT1963A-2.5  [TO-263]
U19  LT1763-1.8  [SO-G8]
U20  LT1763  [SO-G8]

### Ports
PWRSYNC_N (in), PWRSYNC_P (in)

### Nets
12V: C49.1 C51.1 C52.1 C53.1 C62.2 C63.1 C64.1 L3.2 TP8.1 U17.2(VI) U17.10(Track) U20.5(En) U20.8(Vin)
AGND: C61.2
GND: C41.2 C42.1 C43.1 C44.2 C45.2 C46.2 C47.2 C48.1 C49.2 C50.2 C51.2 C52.2 C53.2 C54.2 C55.1 C56.1 C57.2 C59.1 C62.1 C63.2 C64.2 C65.2 C66.2 C67.2 C68.2 C69.2 C70.2 C71.2 C72.2 C73.2 C74.1 C75.1 C76.1 C77.1 C78.1 C79.1 C80.1 C81.1 C82.1 C83.1 C84.1 C85.1 C86.1 C87.1 C88.1 C89.1 C90.1 C91.1 C92.1 C93.1 C94.1 C95.1 C96.1 C97.1 C98.1 C99.1 C100.1 C101.1 C102.1 C103.1 C104.1 C105.1 C106.1 C107.1 C108.1 C109.1 C110.1 C111.1 C112.1 C113.1 C114.1 C115.1 C116.1 C117.1 C118.1 C119.1 C120.1 C121.1 C122.1 C123.1 C124.1 C125.1 C126.1 C127.1 C128.1 C129.1 C130.1 C131.1 C132.1 C133.1 C134.1 C135.1 C136.1 DS3.1(K) P7.2 R37.1 R38.2 R40.2 TP9.1 TP10.1 U15.3(GND) U16.2(GND) U17.3(GND) U17.4(GND) U17.7(Sense-) U18.3(GND) U19.3(GND) U19.6(GND) U19.7(GND) U20.3(GND) U20.6(GND) U20.7(GND)
P10V: C60.1 C61.1 R39.2 TP7.1 U20.1(Vout)
P12V: C48.2 L3.1 P7.1
VCCAUX: C54.1 C56.2 C83.2 C84.2 C85.2 C86.2 C87.2 C88.2 C89.2 C90.2 C91.2 C92.2 C93.2 C94.2 C95.2 C96.2 C97.2 C98.2 C99.2 C101.2 C102.2 C103.2 C104.2 C105.2 C106.2 C107.2 C108.2 C109.2 C110.2 C111.2 C112.2 C113.2 C114.2 C115.2 C116.2 C117.2 C118.2 C119.2 C120.2 C121.2 C122.2 C123.2 C124.2 C125.2 C126.2 C127.2 C128.2 C129.2 C130.2 C131.2 C132.2 C133.2 C134.2 C135.2 C136.2 TP5.1 U18.4(Vout) U18.5(Sens)  [also labelled VCCO_0, VCCO_1, VCCO_2, VCCO_3]
VCCConf: C57.1 C58.1 C59.2 TP6.1 U19.1(Vout) U19.2(Sense)
VCCINT: C41.1 C43.2 C65.1 C66.1 C67.1 C68.1 C69.1 C70.1 C71.1 C72.1 C73.1 C74.2 C75.2 C76.2 C77.2 C78.2 C79.2 C80.2 C81.2 C82.2 TP3.1 U15.4(Vout) U15.5(Sens)
VDD: C42.2 C44.1 C45.1 C46.1 C47.1 C50.1 C55.2 C100.2 R36.2 TP4.1 U15.1(~{Shdn}) U15.2(Vin) U16.1(VCC) U17.5(VO) U17.6(Sense+) U17.9(TT) U18.1(~{Shdn}) U18.2(Vin) U19.5(En) U19.8(Vin)
PWRSYNC_N: U16.4(B) ; port PWRSYNC_N
PWRSYNC_P: U16.3(A) ; port PWRSYNC_P
NetC58_2: C58.2 U19.4(Byp)
NetC60_2: C60.2 U20.4(Byp)
NetDS3_2: DS3.2(A) R36.1
NetR37_2: R37.2 U17.11(Inhibit)
NetR38_1: R38.1 U17.8(Adjust)
NetR39_1: R39.1 R40.1 U20.2(Sense)
NetU16_5: U16.5(R) U17.1(Sync)

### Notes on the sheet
- Power Chassis Timing Interface
- D070071
- B
- Daniel Sigg

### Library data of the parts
C41 C54 C57 = ChipTantalum: Tantalum capacitor, surface mount; Part Number: 399-4131-1-ND; Tolerance: 20%; Voltage Rating: 3V
C42 C49 C55 C61 = ChipCap: Capacitor, surface mount; Part Number: PCC2414CT-ND; Tolerance: 10%; Voltage Rating: 25V
C43 C56 C59 = ChipCap: as C3 on sheet ChassisTimingInterface2
C44-C47 = ChipTantalum: Tantalum capacitor, surface mount; Part Number: 399-4138-1-ND; Tolerance: 20%; Voltage Rating: 4V
C48 C62 C100 = ChipCap: as C1 on sheet ChassisTimingInterface1
C50 = ChipCap: Capacitor, surface mount; Part Number: 490-4539-1-ND; Tolerance: 10%; Voltage Rating: 6.3V
C51-C53 C63 C64 = ChipTantalum: Tantalum capacitor, surface mount; Part Number: 399-3908-1-ND; Tolerance: 20%; Voltage Rating: 25V
C58 C60 = ChipCap: Capacitor, surface mount; Part Number: 490-1642-1-ND; Tolerance: 10%
C65-C68 C74-C77 C83-C90 C101-C104 C110-C113 C119-C122 C128-C131 = ChipCap: Capacitor, surface mount; Part Number: PCC1721CT-ND; Tolerance: 10%
C69 C70 C78 C79 C91-C94 C105 C106 C114 C115 C123 C124 C132 C133 = ChipCap: Capacitor, surface mount; Part Number: 399-3066-1-ND; Tolerance: 10%
C71 C72 C80 C81 C95-C97 C107 C116 C125 C134 = ChipCap: Capacitor, surface mount; Part Number: 587-1456-1-ND; Tolerance: 10%
C73 C98 C108 C117 C126 C135 = ChipCap: Capacitor, surface mount; Part Number: PCC2354CT-ND; Tolerance: 10%
C82 C99 C109 C118 C127 C136 = ChipCap: Capacitor, surface mount; Part Number: 490-1709-1-ND; Tolerance: 10%
DS3 = LED: Panel mount LED; Part Number: 67-1270-ND
L3 = MVR1251: Power inductor. MVR series; Part Number: MVR1251T-561MLB
LOGO4 = LIGO_logo
P7 = TBlock_5.08_2: Terminal block, 5.08mm, 2-Pin; Part Number: 281-1279-ND, 281-1243-ND
R36 = ChipRes1: as R5 on sheet ChassisTimingInterface2
R37 = ChipRes1: Resistor, surface mount; Part Number: RR12P51.1KDCT-ND; Tolerance: 0.5%
R38 = ChipRes1: Resistor, surface mount; Part Number: RG20P1.21KBCT-ND; Tolerance: 0.1%
R39 = ChipRes1: as R22 on sheet ChassisTimingInterface2
R40 = ChipRes1: as R19 on sheet ChassisTimingInterface2
TP3-TP8 = TP_POSITIVE: Testpoint, red; Part Number: 5005K-ND
TP9 TP10 = TP_GND: Testpoint, black; Part Number: 5006K-ND
U15 = LT1963A: 5 Terminal positive LDO regulator, 1.5A; Part Number: LT1963AEQ#PBF-ND
U16 = SN65LVDT2DBV: Single LVDS Receiver with 100 Ohm termination; Part Number: 296-6896-1-ND
U17 = PTH08T240W: Adjustable power module, 10A, 4.5V to 14V input, non-isolated; Part Number: 595-PTH08T240WAZ
U18 = LT1963A: 5 Terminal positive LDO regulator, 1.5A; Part Number: LT1963AEQ-2.5#PBF-ND
U19 = LT1763: Positive voltage regulator; Part Number: LT1763CS8-1.8-ND
U20 = LT1763: Positive voltage regulator; Part Number: LT1763CS8#PBF-ND

## Sheet ChassisTimingInterface3.SchDoc: D070071
size B; Revision: B; SheetNumber: 3; SheetTotal: 6
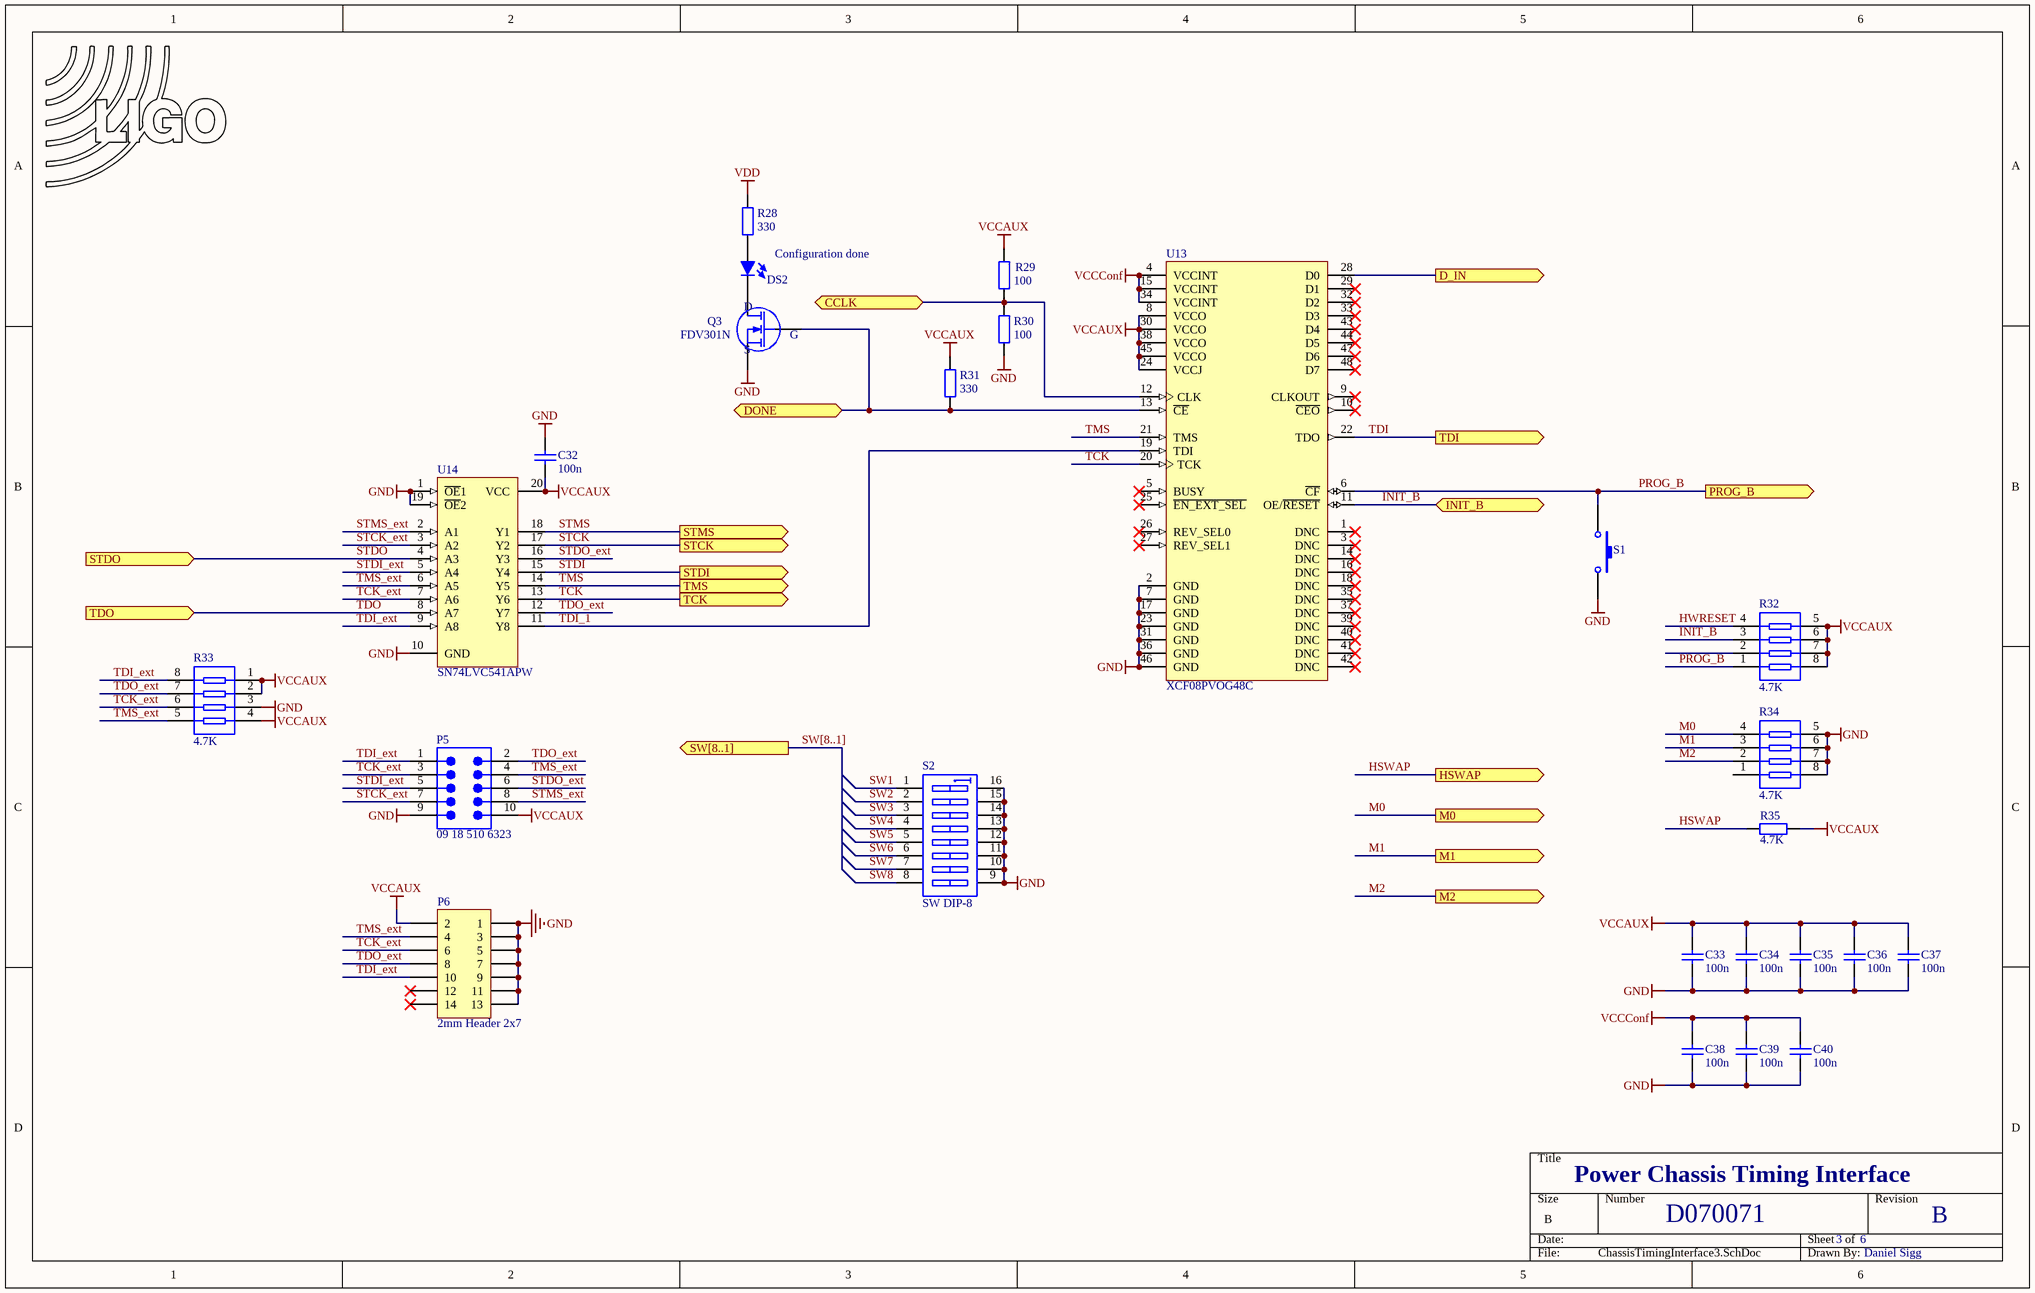
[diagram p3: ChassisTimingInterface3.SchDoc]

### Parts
C32  100n  [CC2013-0805]
C33  100n  [CC2013-0805]
C34  100n  [CC2013-0805]
C35  100n  [CC2013-0805]
C36  100n  [CC2013-0805]
C37  100n  [CC2013-0805]
C38  100n  [CC2013-0805]
C39  100n  [CC2013-0805]
C40  100n  [CC2013-0805]
DS2  LED  [LED-0805]  (value not drawn)
LOGO3  LIGO logo  [LIGO_LOGO]  (value not drawn)  (graphical)
P5  09 18 510 6323  [918510x323]
P6  2mm Header 2x7  [2MM_HDR2X7]
Q3  FDV301N  [SO-G3/C2.25]
R28  330  [CR2012-0805]
R29  100  [CR2012-0805]
R30  100  [CR2012-0805]
R31  330  [CR2012-0805]
R32  value 4.7K  [RES8-0.8]  (hidden comment: Resistor Array)
R33  value 4.7K  [RES8-0.8]  (hidden comment: Resistor Array)
R34  value 4.7K  [RES8-0.8]  (hidden comment: Resistor Array)
R35  4.7K  [CR2012-0805]
S1  B3SN-3112P  [SW_SMD_6MM]  (value not drawn)
S2  SW DIP-8  [DIP_SW_8WAY_SMD]
U13  XCF08PVOG48C  [VOG48]
U14  SN74LVC541APW  [PW020]

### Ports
CCLK (bidir), D_IN (out), DONE (bidir), HSWAP (out), INIT_B (bidir), M0 (out), M1 (out), M2 (out), PROG_B (out), STCK (out), STDI (out), STDO (in), STMS (out), SW[8..1] (out), TCK (out), TDI (out), TDO (in), TMS (out)

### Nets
GND: C32.2 C33.1 C34.1 C35.1 C36.1 C37.1 C38.1 C39.1 C40.1 P5.9 P6.1 P6.3 P6.5 P6.7 P6.9 P6.11 P6.13 Q3.2(S) R30.2 R33.3 R34.5 R34.6 R34.7 R34.8 S1.2 S1.5 S2.9(B8) S2.10(B7) S2.11(B6) S2.12(B5) S2.13(B4) S2.14(B3) S2.15(B2) S2.16(B1) U13.2(GND) U13.7(GND) U13.17(GND) U13.23(GND) U13.31(GND) U13.36(GND) U13.46(GND) U14.1(~{OE}1) U14.10(GND) U14.19(~{OE}2)
VCCAUX: C32.1 C33.2 C34.2 C35.2 C36.2 C37.2 P5.10 P6.2 R29.1 R31.1 R32.5 R32.6 R32.7 R32.8 R33.1 R33.2 R33.4 R35.2 U13.8(VCCO) U13.24(VCCJ) U13.30(VCCO) U13.38(VCCO) U13.45(VCCO) U14.20(VCC)
VCCConf: C38.2 C39.2 C40.2 U13.4(VCCINT) U13.15(VCCINT) U13.34(VCCINT)
VDD: R28.1
CCLK: R29.2 R30.1 U13.12(CLK) ; port CCLK
D_IN: U13.28(D0) ; port D_IN
DONE: Q3.1(G) R31.2 U13.13(~{CE}) ; port DONE
HSWAP: R35.1 ; port HSWAP
HWRESET: R32.4
INIT_B: R32.3 U13.11(OE/~{RESET}) ; port INIT_B
M0: R34.4 ; port M0
M1: R34.3 ; port M1
M2: R34.2 ; port M2
PROG_B: R32.1 S1.1 U13.6(~{CF}) ; port PROG_B
STCK: U14.17(Y2) ; port STCK
STCK_ext: P5.7 U14.3(A2)
STDI: U14.15(Y4) ; port STDI
STDI_ext: P5.5 U14.5(A4)
STDO: U14.4(A3) ; port STDO
STDO_ext: P5.6 U14.16(Y3)
STMS: U14.18(Y1) ; port STMS
STMS_ext: P5.8 U14.2(A1)
SW1: S2.1(A1)
SW2: S2.2(A2)
SW3: S2.3(A3)
SW4: S2.4(A4)
SW5: S2.5(A5)
SW6: S2.6(A6)
SW7: S2.7(A7)
SW8: S2.8(A8)
TCK: U13.20(TCK) U14.13(Y6) ; port TCK
TCK_ext: P5.3 P6.6 R33.6 U14.7(A6)
TDI: U13.22(TDO) ; port TDI  [project net TDI_A]
TDI_1: U13.19(TDI) U14.11(Y8)
TDI_ext: P5.1 P6.10 R33.8 U14.9(A8)
TDO: U14.8(A7) ; port TDO
TDO_ext: P5.2 P6.8 R33.7 U14.12(Y7)
TMS: U13.21(TMS) U14.14(Y5) ; port TMS
TMS_ext: P5.4 P6.4 R33.5 U14.6(A5)
NetDS2_1: DS2.1(K) Q3.3(D)
NetDS2_2: DS2.2(A) R28.2

Not connected (* = marked no-connect by the designer): P6 12* 14*; R32 2; R34 1; S1 3 4; U13 1(DNC)* 3(DNC)* 5(BUSY)* 9(CLKOUT)* 10(~{CEO})* 14(DNC)* 16(DNC)* 18(DNC)* 25(~{EN_EXT_SEL})* 26(REV_SEL0)* 27(REV_SEL1)* 29(D1)* 32(D2)* 33(D3)* 35(DNC)* 37(DNC)* 39(DNC)* 40(DNC)* 41(DNC)* 42(DNC)* 43(D4)* 44(D5)* 47(D6)* 48(D7)*

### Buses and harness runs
bus SW[8..1] = port SW[8..1]

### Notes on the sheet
- Configuration done
- Power Chassis Timing Interface
- D070071
- B
- Daniel Sigg

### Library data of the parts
C32-C40 = ChipCap: as C1 on sheet ChassisTimingInterface1
DS2 = LED: Surface mount LED; Part Number: 67-1553-1-ND
LOGO3 = LIGO_logo
P5 = 09 18 510 6323: Flat Cable Connector (IDC), Low-Profile Male Header, Angled Solder Pin, 10 Contacts, Performance Level 2; Part Number: A33180-ND
P6 = Xilinx_JTAG_Header: Xilinx JTAG header, 7-Pin, Dual row; Part Number: WM17469-ND
Q3 = FDV301N: as Q1 on sheet ChassisTimingInterface1
R28 R31 = ChipRes1: Resistor, surface mount; Part Number: RR12P330DCT-ND; Tolerance: 0.5%
R29 R30 = ChipRes1: as R5 on sheet ChassisTimingInterface2
R32-R34 = RES4_ARRAY: as R6 on sheet ChassisTimingInterface2
R35 = ChipRes1: as R4 on sheet ChassisTimingInterface1
S1 = B3SN-3112P: Switch, SMD, 6mm; Part Number: SW262CT-ND
S2 = SW DIP-8: DIP Switch, 8 Position, SPST; Part Number: 450-1343-ND
U13 = XCF08PVOG48C: XCF00P Series, Platform Flash In-System Programmable Configuration 1.8V PROM, 48-Pin TSSOP, Pb-Free, 8-Megabit, Commercial Grade; Part Number: 122-1454-5-ND
U14 = SN74LVC541APWLE: Octal Buffer/Driver with 3-State Outputs; Part Number: 296-8521-1-ND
